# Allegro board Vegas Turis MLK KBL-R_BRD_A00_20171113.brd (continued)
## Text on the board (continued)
User.32: ByImpedance:100.0@_REF_L2=("3.5/9.5(L1/L3)")|_REF_L1=("4.0/4.5(L2)")|_REF_L6=("4.0/4.5(L5)")|Type="DP"|_REF_L4=("3.5/5.5(L3/L5)" "4.0/6.0(L2/L5)")|_REF_L3=("4.0/6.0(L2/L5)")|imp="100.0" | ByImpedance:37.5@_REF_L2=("7.0(L1/L3)")|_REF_L1=("13.0(L2)")|_REF_L6=("13.0(L5)")|Type="SE"|_REF_L4=("11.5(L2/L5)" "11.0(L3/L5)")|_REF_L3=("11.5(L2/L5)")|imp="37.5" | ByImpedance:40.0@_REF_L2=("6.0(L1/L3)")|_REF_L1=("11.5(L2)")|_REF_L6=("11.5(L5)")|Type="SE"|_REF_L4=("10.5(L2/L5)" "10.0(L3/L5)")|_REF_L3=("10.5(L2/L5)")|imp="40.0" | ByImpedance:42.0@_REF_L2=("5.5(L1/L3)")|_REF_L1=("11.0(L2)")|_REF_L6=("11.0(L5)")|Type="SE"|_REF_L4=("9.0(L3/L5)" "9.5(L2/L5)")|_REF_L3=("9.5(L2/L5)")|imp="42.0" | ByImpedance:45.0@_REF_L2=("5.0(L1/L3)")|_REF_L1=("9.0(L2)")|_REF_L6=("9.0(L5)")|Type="SE"|_REF_L4=("8.0(L2/L5)" "8.0(L3/L5)")|_REF_L3=("8.0(L2/L5)")|imp="45.0" | ByImpedance:50.0@_REF_L2=("3.5(L1/L3)")|_REF_L1=("7.5(L2)")|_REF_L6=("7.5(L5)")|Type="SE"|_REF_L4=("6.5(L2/L5)" "6.5(L3/L5)")|_REF_L3=("6.5(L2/L5)")|imp="50.0" | ByImpedance:55.0@_REF_L1=("6.0(L2)")|_REF_L6=("6.0(L5)")|Type="SE"|_REF_L4=("5.0(L3/L5)" "5.0(L2/L5)")|_REF_L3=("5.0(L2/L5)")|imp="55.0" | ByImpedance:70.0@_REF_L2=("6.0/4.0(L1/L3)")|_REF_L1=("11.0/5.0(L2)")|_REF_L6=("11.0/5.0(L5)")|Type="DP"|_REF_L4=("9.0/5.0(L2/L5)" "8.0/4.0(L3/L5)")|_REF_L3=("9.0/5.0(L2/L5)")|imp="70.0" | ByImpedance:80.0@_REF_L2=("4.5/4.0(L1/L3)")|_REF_L1=("8.0/5.0(L2)")|_REF_L6=("8.0/5.0(L5)")|Type="DP"|_REF_L4=("5.5/4.0(L3/L5)" "6.5/5.0(L2/L5)")|_REF_L3=("6.5/5.0(L2/L5)")|imp="80.0" | ByImpedance:83.0@_REF_L2=("4.0/4.0(L1/L3)")|_REF_L1=("7.5/5.5(L2)")|_REF_L6=("7.5/5.5(L5)")|Type="DP"|_REF_L4=("6.0/5.0(L2/L5)" "6.0/5.0(L3/L5)")|_REF_L3=("6.0/5.0(L2/L5)")|imp="83.0" | ByImpedance:85.0@_REF_L2=("4.0/4.5(L1/L3)")|_REF_L1=("7.0/5.0(L2)")|_REF_L6=("7.0/5.0(L5)")|Type="DP"|_REF_L4=("5.0/4.5(L3/L5)" "6.0/5.5(L2/L5)")|_REF_L3=("6.0/5.5(L2/L5)")|imp="85.0" | ByImpedance:88.0@_REF_L2=("3.5/4.0(L1/L3)")|_REF_L1=("6.0/4.5(L2)")|_REF_L6=("6.0/4.5(L5)")|Type="DP"|_REF_L4=("4.5/4.5(L3/L5)" "6.0/6.5(L2/L5)")|_REF_L3=("6.0/6.5(L2/L5)")|imp="88.0" | ByImpedance:90.0@_REF_L2=("3.5/4.5(L1/L3)")|_REF_L1=("6.0/5.0(L2)")|_REF_L6=("6.0/5.0(L5)")|Type="DP"|_REF_L4=("6.0/7.5(L2/L5)" "4.0/4.0(L3/L5)")|_REF_L3=("6.0/7.5(L2/L5)")|imp="90.0" | LayerIndex:nil | Source:6-1.2-17a.xls | artWorks:("_REF_L3" "_REF_L2" "_REF_L4" "_REF_L6" "_REF_L1") | gtImpOutlineUsed:BOARD GEOMETRY/PANEL_OUTLINE
User.33: Board Accuracy Check,Nov 09 16:26:10 2017,Passed | Dummy-Static-No Shape On Layer Check,Nov 09 16:26:11 2017,147 errors | Split Plane Check,Nov 09 16:26:10 2017,147 errors
User.41: This gerber is just for your reference to find the DP impedance traces in layer L1. | DP IMPEDANCE TABLE: L1 | * - Denotes that this Impedance | is NOT used | IMP(Ohm) | *70.0 | 80.0 | *83.0 | 85.0 | *88.0 | *90.0 | 100.0 | WIDTH(mils) | 11.0/5.0 | 8.0/5.0 | 7.5/5.5 | 7.0/5.0 | 6.0/4.5 | 6.0/5.0 | 4.0/4.5 | TYPE | DP | Ref. Plane | L2
User.43: This gerber is just for your reference to find the SE impedance traces in layer L1. | SE IMPEDANCE TABLE: L1 | * - Denotes that this Impedance | is NOT used | IMP(Ohm) | *37.5 | *40.0 | *42.0 | *45.0 | 50.0 | *55.0 | WIDTH(mils) | 13.0 | 11.5 | 11.0 | 9.0 | 7.5 | 6.0 | TYPE | SE | Ref. Plane | L2
User.45: Note:Refer to DRILL layer for ELLIPSE drill direction | FIGURE | SIZE | 10.0 | 12.0 | 16.0 | 21.0 | 26.0 | 28.0 | 36.0 | 40.0 | 91.0 | 115.0 | 128.0 | 178.0 | 44.0 | 46.0 | 48.0 | 52.0 | 63.0 | 65.0 | 103.0 | 158.0 | 71.0x36.0 | 83.0x28.0 | 95.0x28.0 | 98.0x28.0 | 99.0x24.0 | 106.0x28.0 | 158.0x119.0 | DRILL CHART: TOP to BOTTOM | ALL UNITS ARE IN MILS | PLATED | NON-PLATED | QTY | 4062 | 82 | 786 | 19 | 15 | 18 | 8 | 1 | 2 | 6 | 4 | This gerber is just for your reference to find the DP impedance traces in layer L2. | This gerber is just for your reference to find the DP impedance traces in layer L3. | This gerber is just for your reference to find the DP impedance traces in layer L4. | This gerber is just for your reference to find the DP impedance traces in layer L6. | This gerber is just for your reference to find the SE impedance traces in layer L2. | This gerber is just for your reference to find the SE impedance traces in layer L3. | This gerber is just for your reference to find the SE impedance traces in layer L4. | This gerber is just for your reference to find the SE impedance traces in layer L6. | DP IMPEDANCE TABLE: L2 | DP IMPEDANCE TABLE: L3 | DP IMPEDANCE TABLE: L4 | DP IMPEDANCE TABLE: L6 | SE IMPEDANCE TABLE: L2 | SE IMPEDANCE TABLE: L3 | SE IMPEDANCE TABLE: L4 | SE IMPEDANCE TABLE: L6 | * - Denotes that this Impedance | is NOT used | Model | Vegas/Turis MLK KBL-R | PCB_NO | 17841 | VER. | Layer | DRILL | L1 | L2 | L3 | TMASK | TPLACE | TSILK | TSMD | Designer | ANNE | Date | 11/09/2017 | IMP(Ohm) | *37.5 | *70.0 | *40.0 | *80.0 | 80.0 | *42.0 | *83.0 | 83.0 | *45.0 | *85.0 | 45.0 | 85.0 | *88.0 | 50.0 | *55.0 | *90.0 | *100.0 | 100.0 | WIDTH(mils) | 13.0 | 7.0 | 11.5 | 6.0 | 11.0 | 5.5 | 5.0 | 9.0 | 3.5 | 7.5 | 10.5 | 9.5 | 8.0 | 6.5 | 11.0/5.0 | 8.0/5.0 | 7.5/5.5 | 7.0/5.0 | 6.0/4.5 | 6.0/5.0 | 4.0/4.5 | 6.0/4.0 | 9.0/5.0 | 4.5/4.0 | 6.5/5.0 | 8.0/4.0 | 4.0/4.0 | 5.5/4.0 | 6.0/5.5 | 3.5/4.0 | 6.0/6.5 | 3.5/4.5 | 6.0/7.5 | 3.5/9.5 | 4.0/6.0 | 5.0/4.5 | 4.5/4.5 | 3.5/5.5 | TYPE | SE | DP | Ref. Plane | L1/L3 | L5 | L2/L5 | L3/L5 | BMASK | BPLACE | BSILK | BSMD | L4 | L5GND | L6
